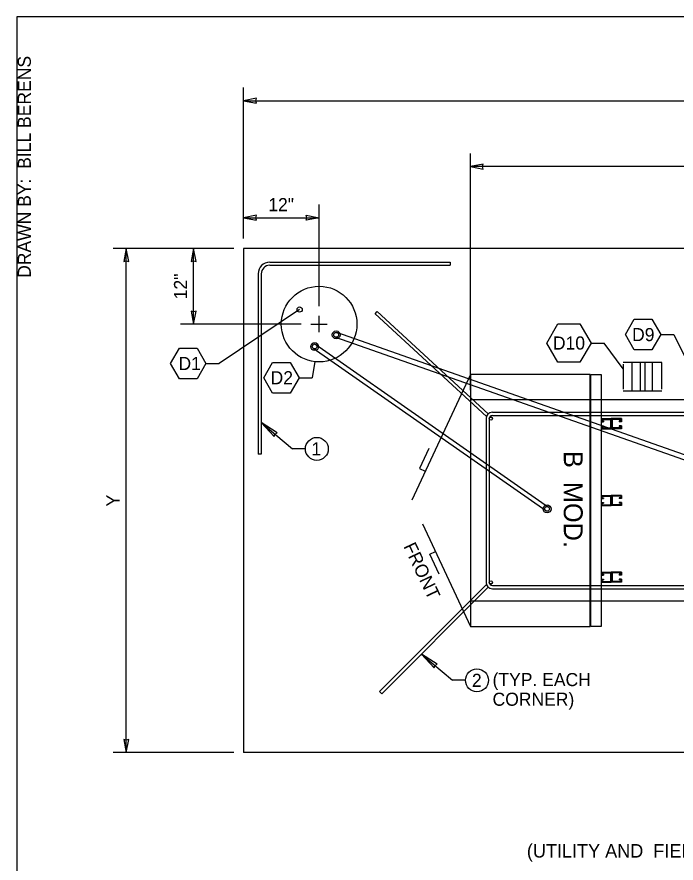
# Model space of a CAD drawing. Extents: x 99862 to 103151, y 100000 to 117076.
# Drawn here: x 99862 to 100667, y 113042 to 114076 of the extents above; entities that cross this region are included whole.
import ezdxf

# ---------------------------------------------------------------- set-up
doc = ezdxf.new("R2010")
doc.units = 0
for name, color, linetype in [('Default', 7, 'Continuous'), ('Level 1', 7, 'Continuous'), ('Level 10', 7, 'Continuous'), ('Level 11', 7, 'Continuous'), ('Level 15', 7, 'Continuous'), ('Level 20', 7, 'Continuous'), ('Level 30', 7, 'Continuous'), ('Level 40', 7, 'Continuous'), ('Level 62', 7, 'Continuous'), ('Level 7', 7, 'Continuous')]:
    doc.layers.add(name, color=color, linetype=linetype)

msp = doc.modelspace()

# ---------------------------------------------------------------- linework, layer by layer
at = {"layer": 'Default'}
for p, q in [((100170.7, 113775.9), (100391.1, 113775.9)), ((100170.7, 113772.1), (100391.1, 113772.1)), ((100391.1, 113775.9), (100391.1, 113772.1)), ((100156.6, 113761.8), (100156.6, 113541.4)), ((100160.5, 113761.8), (100160.5, 113541.4)), ((100299.5, 113712.7), (100302.1, 113715.5)), ((100299.5, 113712.7), (100435.4, 113587.3)), ((100302.1, 113715.5), (100437.5, 113590.5)), ((100435, 113584.9), (100435, 113384.8)), ((100438.9, 113584.9), (100438.9, 113384.8)), ((100438.9, 113584), (100439.5, 113583.5)), ((100440.3, 113587.9), (100442.1, 113586.3)), ((100442.7, 113592.6), (101300.7, 113592.6)), ((100442.7, 113588.7), (101300.7, 113588.7)), ((100160.5, 113541.4), (100156.6, 113541.4)), ((100304.7, 113251.5), (100435.5, 113382.2)), ((100307.5, 113248.8), (100437.7, 113379)), ((100438.9, 113385.6), (100439.4, 113386.2)), ((100440.4, 113381.7), (100442.1, 113383.5)), ((100442.7, 113381), (101300.7, 113381)), ((100442.7, 113377.1), (101300.7, 113377.1)), ((100304.7, 113251.5), (100307.5, 113248.8))]:
    msp.add_line(p, q, dxfattribs=at)
for centre in [(100440.8, 113584.9), (100440.8, 113384.8)]:
    msp.add_circle(centre, 1.92, dxfattribs=at)
for centre, radius, start, end in [((100170.7, 113761.8), 14.1, 90, 180), ((100170.7, 113761.8), 10.3, 90, 180), ((100442.7, 113584.9), 7.7, 90, 180), ((100442.7, 113584.9), 3.85, 90, 180), ((100442.7, 113384.8), 7.7, 180, 270), ((100442.7, 113384.8), 3.85, 180, 270)]:
    msp.add_arc(centre, radius, start, end, dxfattribs=at)
at = {"layer": 'Level 1'}
for p, q in [((101404.5, 113284.1), (100252.9, 113689.9)), ((100251, 113684.5), (101402.6, 113278.7)), ((100507.9, 113472.2), (100223.9, 113670.5)), ((100227.2, 113675.2), (100511.2, 113476.9))]:
    msp.add_line(p, q, dxfattribs=at)
msp.add_lwpolyline([(99862, 111999.5), (103151, 111999.5), (103151, 114075.5), (99862, 114075.5)], close=True, dxfattribs=at)
for centre, radius in [((100207.3, 113718.1), 3.13), ((100251.9, 113687.2), 4.81), ((100251.9, 113687.2), 2.89), ((100225.6, 113672.8), 4.81), ((100225.6, 113672.8), 2.89), ((100509.5, 113474.6), 4.81), ((100509.5, 113474.6), 2.89)]:
    msp.add_circle(centre, radius, dxfattribs=at)
at = {"layer": 'Level 10'}
for p, q in [((100623.1, 113653.5), (100623.1, 113618.8)), ((100628.9, 113653.5), (100628.9, 113618.8))]:
    msp.add_line(p, q, dxfattribs=at)
at = {"layer": 'Level 11'}
for p, q in [((100646.6, 113792.7), (100138.8, 113792.7)), ((100138.8, 113792.7), (100138.8, 113177.1)), ((100923.6, 113792.7), (100646.6, 113792.7)), ((100646.6, 113608), (100415.8, 113608)), ((100415.8, 113608), (100415.8, 113361.7)), ((100923.6, 113608), (100646.6, 113608)), ((100646.6, 113361.7), (100415.8, 113361.7)), ((100923.6, 113361.7), (100646.6, 113361.7)), ((100646.6, 113177.1), (100138.8, 113177.1)), ((100877.5, 113177.1), (100646.6, 113177.1))]:
    msp.add_line(p, q, dxfattribs=at)
msp.add_circle((100231.1, 113700.3), 46.2, dxfattribs=at)
at = {"layer": 'Level 15'}
for p, q in [((100138.8, 113804.7), (100138.8, 113989.1)), ((100138.8, 113973.1), (101512.3, 113973.1)), ((100415.8, 113619.8), (100415.8, 113908.7)), ((101327.6, 113892.7), (100415.8, 113892.7)), ((100231.1, 113722.3), (100231.1, 113846.2)), ((100138.8, 113830.2), (100231.1, 113830.2)), ((100126.8, 113792.7), (99979.4, 113792.7)), ((99995.4, 113177.1), (99995.4, 113792.7)), ((100077.8, 113700.3), (100077.8, 113792.7)), ((100207.3, 113718.1), (100108.9, 113652.2)), ((100231.1, 113690.3), (100231.1, 113710.3)), ((100209.1, 113700.3), (100061.8, 113700.3)), ((100221.1, 113700.3), (100241.1, 113700.3)), ((100648.4, 113687.5), (100664.4, 113687.5)), ((100664.4, 113687.5), (100709.2, 113595.4)), ((100563.2, 113677.2), (100579.2, 113677.2)), ((100602.4, 113645.6), (100579.2, 113677.2)), ((100092.9, 113652.2), (100108.9, 113652.2)), ((100225.8, 113654.5), (100222.7, 113634.8)), ((100206.7, 113634.8), (100222.7, 113634.8)), ((100160.5, 113580), (100198.4, 113547.9)), ((100214.3, 113547.9), (100198.3, 113547.9)), ((100356, 113297.3), (100393.9, 113265.2)), ((100409.8, 113265.2), (100393.8, 113265.2)), ((100126.8, 113177.1), (99979.4, 113177.1))]:
    msp.add_line(p, q, dxfattribs=at)
for points in [[(100138.8, 113973.1), (100154.5, 113970), (100153.7, 113973.1), (100154.5, 113976.2)], [(100415.8, 113892.7), (100431.5, 113889.6), (100430.8, 113892.7), (100431.5, 113895.7)], [(100138.8, 113830.2), (100154.5, 113827.1), (100153.7, 113830.2), (100154.5, 113833.3)], [(100231.1, 113830.2), (100215.4, 113827.1), (100216.1, 113830.2), (100215.4, 113833.3)], [(99995.4, 113792.7), (99992.4, 113776.9), (99995.4, 113777.7), (99998.5, 113776.9)], [(100077.8, 113792.7), (100074.7, 113776.9), (100077.8, 113777.7), (100080.9, 113776.9)], [(100077.8, 113700.3), (100080.9, 113716), (100077.8, 113715.3), (100074.7, 113716)], [(100160.5, 113580), (100176, 113562.9), (100177.1, 113565.9), (100179.8, 113567.5)], [(100356, 113297.3), (100371.5, 113280.3), (100372.6, 113283.2), (100375.3, 113284.8)], [(99995.4, 113177.1), (99998.5, 113192.8), (99995.4, 113192.1), (99992.4, 113192.8)]]:
    msp.add_lwpolyline(points, close=True, dxfattribs=at)
at = {"layer": 'Level 20'}
for points in [[(100509.1, 113677.2), (100522.6, 113700.6), (100549.6, 113700.6), (100563.2, 113677.2), (100549.6, 113653.7), (100522.6, 113653.7), (100509.1, 113677.2)], [(100605.1, 113687.5), (100615.9, 113706.3), (100637.6, 113706.3), (100648.4, 113687.5), (100637.6, 113668.8), (100615.9, 113668.8), (100605.1, 113687.5)], [(100049.6, 113652.2), (100060.4, 113670.9), (100082, 113670.9), (100092.9, 113652.2), (100082, 113633.4), (100060.4, 113633.4), (100049.6, 113652.2)], [(100163.5, 113634.8), (100174.3, 113653.6), (100195.9, 113653.6), (100206.7, 113634.8), (100195.9, 113616.1), (100174.3, 113616.1), (100163.5, 113634.8)]]:
    msp.add_lwpolyline(points, dxfattribs=at)
for centre in [(100228.3, 113547.9), (100423.8, 113265.2)]:
    msp.add_circle(centre, 14, dxfattribs=at)
at = {"layer": 'Level 30'}
for p, q in [((100602.4, 113651.5), (100602.4, 113620.8)), ((100613.6, 113618.8), (100613.6, 113653.5)), ((100638.3, 113618.8), (100638.3, 113653.5)), ((100649.5, 113651.5), (100649.5, 113653.5)), ((100649.5, 113620.8), (100649.5, 113651.5))]:
    msp.add_line(p, q, dxfattribs=at)
for points in [[(100649.5, 113653.5), (100649.5, 113653.5), (100602.4, 113653.5), (100602.4, 113653.5)], [(100602.4, 113618.8), (100649.5, 113618.8), (100649.5, 113618.8)]]:
    msp.add_lwpolyline(points, dxfattribs=at)
at = {"layer": 'Level 40'}
for p, q in [((100415.8, 113638.8), (100344.2, 113485.3)), ((100575.4, 113584.9), (100587.9, 113584.9)), ((100575.4, 113584.9), (100575.4, 113581)), ((100600.5, 113584.9), (100587.9, 113584.9)), ((100587.9, 113584.9), (100587.9, 113572.4)), ((100587.9, 113584.9), (100587.9, 113572.4)), ((100600.5, 113584.9), (100600.5, 113581)), ((100575.4, 113581.1), (100578.4, 113581.1)), ((100575.4, 113576.2), (100578.4, 113576.2)), ((100575.4, 113576.2), (100575.4, 113572.4)), ((100576.4, 113583.9), (100587, 113583.9)), ((100576.4, 113583.9), (100576.4, 113582)), ((100576.4, 113582), (100578.4, 113582)), ((100576.4, 113575.2), (100578.4, 113575.2)), ((100576.4, 113575.2), (100576.4, 113573.4)), ((100578.4, 113582), (100578.4, 113581.1)), ((100578.4, 113576.2), (100578.4, 113575.2)), ((100587, 113583.9), (100587, 113573.4)), ((100599.5, 113583.9), (100588.9, 113583.9)), ((100588.9, 113583.9), (100588.9, 113573.4)), ((100599.5, 113582), (100597.5, 113582)), ((100597.5, 113582), (100597.5, 113581.1)), ((100600.5, 113581.1), (100597.5, 113581.1)), ((100600.5, 113576.2), (100597.5, 113576.2)), ((100597.5, 113576.2), (100597.5, 113575.2)), ((100599.5, 113575.2), (100597.5, 113575.2)), ((100599.5, 113583.9), (100599.5, 113582)), ((100599.5, 113575.2), (100599.5, 113573.4)), ((100600.5, 113576.2), (100600.5, 113572.4)), ((100575.4, 113572.4), (100587.9, 113572.4)), ((100576.4, 113573.4), (100587, 113573.4)), ((100600.5, 113572.4), (100587.9, 113572.4)), ((100599.5, 113573.4), (100588.9, 113573.4)), ((100365.2, 113548.4), (100353.8, 113524)), ((100353.8, 113524), (100360.8, 113520.8)), ((100575.4, 113491.1), (100587.9, 113491.1)), ((100575.4, 113491.1), (100575.4, 113487.2)), ((100600.5, 113491.1), (100587.9, 113491.1)), ((100587.9, 113491.1), (100587.9, 113478.6)), ((100587.9, 113491.1), (100587.9, 113478.6)), ((100600.5, 113491.1), (100600.5, 113487.2)), ((100575.4, 113487.3), (100578.4, 113487.3)), ((100575.4, 113482.4), (100578.4, 113482.4)), ((100575.4, 113482.4), (100575.4, 113478.6)), ((100576.4, 113490.1), (100587, 113490.1)), ((100576.4, 113490.1), (100576.4, 113488.2)), ((100576.4, 113488.2), (100578.4, 113488.2)), ((100576.4, 113481.5), (100578.4, 113481.5)), ((100576.4, 113481.5), (100576.4, 113479.6)), ((100578.4, 113488.2), (100578.4, 113487.3)), ((100578.4, 113482.4), (100578.4, 113481.5)), ((100587, 113490.1), (100587, 113479.6)), ((100599.5, 113490.1), (100588.9, 113490.1)), ((100588.9, 113490.1), (100588.9, 113479.6)), ((100599.5, 113488.2), (100597.5, 113488.2)), ((100597.5, 113488.2), (100597.5, 113487.3)), ((100600.5, 113487.3), (100597.5, 113487.3)), ((100600.5, 113482.4), (100597.5, 113482.4)), ((100597.5, 113482.4), (100597.5, 113481.5)), ((100599.5, 113481.5), (100597.5, 113481.5)), ((100599.5, 113490.1), (100599.5, 113488.2)), ((100599.5, 113481.5), (100599.5, 113479.6)), ((100600.5, 113482.4), (100600.5, 113478.6)), ((100575.4, 113478.6), (100587.9, 113478.6)), ((100576.4, 113479.6), (100587, 113479.6)), ((100600.5, 113478.6), (100587.9, 113478.6)), ((100599.5, 113479.6), (100588.9, 113479.6)), ((100357.2, 113456.5), (100415.8, 113331)), ((100366.1, 113419.3), (100373.1, 113422.5)), ((100377.5, 113394.9), (100366.1, 113419.3)), ((100575.4, 113397.5), (100587.9, 113397.5)), ((100575.4, 113397.5), (100575.4, 113393.7)), ((100575.4, 113393.7), (100578.4, 113393.7)), ((100575.4, 113388.8), (100578.4, 113388.8)), ((100575.4, 113388.8), (100575.4, 113385)), ((100576.4, 113396.6), (100587, 113396.6)), ((100576.4, 113396.6), (100576.4, 113394.7)), ((100576.4, 113394.7), (100578.4, 113394.7)), ((100576.4, 113387.9), (100578.4, 113387.9)), ((100576.4, 113387.9), (100576.4, 113386)), ((100578.4, 113394.7), (100578.4, 113393.7)), ((100578.4, 113388.8), (100578.4, 113387.9)), ((100587, 113396.6), (100587, 113386)), ((100600.5, 113397.5), (100587.9, 113397.5)), ((100587.9, 113397.5), (100587.9, 113385)), ((100587.9, 113397.5), (100587.9, 113385)), ((100599.5, 113396.6), (100588.9, 113396.6)), ((100588.9, 113396.6), (100588.9, 113386)), ((100599.5, 113394.7), (100597.5, 113394.7)), ((100597.5, 113394.7), (100597.5, 113393.7)), ((100600.5, 113393.7), (100597.5, 113393.7)), ((100600.5, 113388.8), (100597.5, 113388.8)), ((100597.5, 113388.8), (100597.5, 113387.9)), ((100599.5, 113387.9), (100597.5, 113387.9)), ((100599.5, 113396.6), (100599.5, 113394.7)), ((100599.5, 113387.9), (100599.5, 113386)), ((100600.5, 113397.5), (100600.5, 113393.7)), ((100600.5, 113388.8), (100600.5, 113385)), ((100575.4, 113385), (100587.9, 113385)), ((100576.4, 113386), (100587, 113386)), ((100600.5, 113385), (100587.9, 113385)), ((100599.5, 113386), (100588.9, 113386))]:
    msp.add_line(p, q, dxfattribs=at)
for points in [[(100415.8, 113638.8), (100415.8, 113331), (100562, 113331), (100562, 113638.8)], [(100575.4, 113638.9), (100575.4, 113331.1), (100562.9, 113331.1), (100562.9, 113638.9)]]:
    msp.add_lwpolyline(points, close=True, dxfattribs=at)

# ---------------------------------------------------------------- texts
at = {"layer": 'Level 20'}
for s, height, p in [('12"', 16, (100169, 113838.2)), ('D9', 16, (100613.3, 113679.5)), ('D10', 16, (100516.6, 113669.2)), ('D1', 16, (100059.3, 113644.2)), ('D2', 16, (100171.8, 113626.8)), ('1', 16, (100221.7, 113539.9)), ('(TYP. EACH', 16, (100442.9, 113258.1)), ('2', 16, (100417.7, 113257.2)), ('CORNER)', 16, (100442.9, 113234.1)), ('(UTILITY AND  FIELD CONDUITS NOT SHOWN FOR CLARITY)', 16.5, (100484.8, 113048.7))]:
    msp.add_text(s, height=height, dxfattribs=at).set_placement(p)
for s, rotation, p in [('12"', 90, (100069.8, 113730.6)), ('Y', 90, (99987.4, 113477.6)), ('FRONT', 295.2784, (100333.7, 113428.9))]:
    msp.add_text(s, height=16, rotation=rotation, dxfattribs=at).set_placement(p)
at = {"layer": 'Level 62'}
msp.add_text('DRAWN BY:  BILL BERENS', height=16, rotation=90, dxfattribs=at).set_placement((99879, 113756.8))
at = {"layer": 'Level 7'}
msp.add_text('B  MOD.', height=23.09, rotation=270, dxfattribs=at).set_placement((100529.9, 113545.3))

doc.saveas('drawing.dxf')
